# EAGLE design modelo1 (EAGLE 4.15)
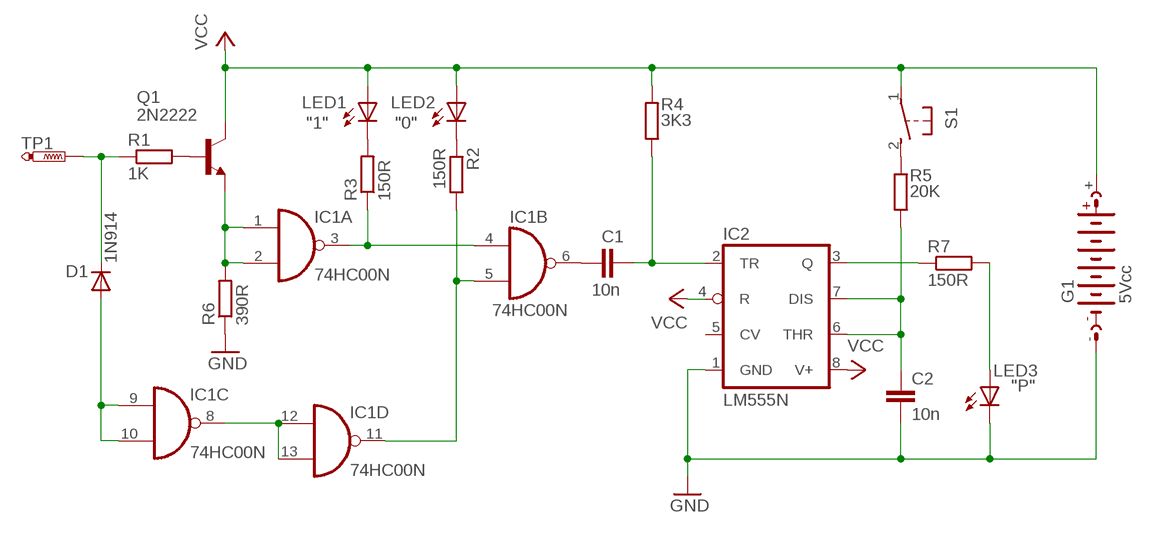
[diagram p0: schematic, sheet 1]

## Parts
C1  10n  C-EU050-030X075  [C050-030X075]
C2  10n  C-EU050-030X075  [C050-030X075]
D1  1N914  DIODE-D-5  [D-5]
G1  5Vcc  AB9V  [AB9V]
IC1  74HC00N  [DIL14]
IC2  LM555N  [DIL08]
LED1  "1"  LED3MM  [LED3MM]
LED2  "0"  LED3MM  [LED3MM]
LED3  "P"  LED3MM  [LED3MM]
Q1  2N2222  [TO18]
R1  1K  R-EU_0204/7  [0204/7]
R2  150R  R-EU_0204/7  [0204/7]
R3  150R  R-EU_0204/7  [0204/7]
R4  3K3  R-EU_0204/7  [0204/7]
R5  20K  R-EU_0204/7  [0204/7]
R6  390R  R-EU_0204/7  [0204/7]
R7  150R  R-EU_0204/7  [0204/7]
S1  31-XX  [B3F-31XX]
TP1  PTR1PAD1-17  [P1-17]

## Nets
GND: C2.2 G1.- IC2.1(GND) LED3.K(C) R6.1
N$1: D1.C R1.1 TP1.1(TP)
N$2: Q1.2(B) R1.2
N$3: LED2.K(C) R2.1
N$4: LED1.K(C) R3.2
N$5: IC1.3(A:O) IC1.4(B:I0) R3.1
N$6: IC1.5(B:I1) IC1.11(D:O) R2.2
N$7: C1.1 IC1.6(B:O)
N$8: IC1.1(A:I0) IC1.2(A:I1) Q1.1(E) R6.2
N$9: D1.A IC1.9(C:I0) IC1.10(C:I1)
N$10: IC1.8(C:O) IC1.12(D:I0) IC1.13(D:I1)
N$11: C1.2 IC2.2(TR) R4.1
N$12: IC2.3(Q) R7.1
N$13: C2.1 IC2.6(THR) IC2.7(DIS) R5.1
N$14: R5.2 S1.2(S)
N$15: LED3.A R7.2
VCC: G1.+ IC2.4(R) IC2.8(V+) LED1.A LED2.A Q1.3(C) R4.2 S1.1(P)
Unconnected: IC2.5(CV)

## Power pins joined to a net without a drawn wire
GND: IC1.7(P:GND)
VCC: IC1.14(P:VCC)

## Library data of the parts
C1 C2 = rcl:C-EU: CAPACITOR, European symbol
D1 = diode:DIODE-: DIODE
G1 = battery:AB9V: 9-V BATTERY CLIP
IC1 = 74xx-eu:74*00: Quad 2-input NAND gate
IC2 = linear:*555: TIMER
LED1-LED3 = led:LED: LED
Q1 = transistor-npn:2N2222*: NPN Transistor
R1-R7 = rcl:R-EU_: RESISTOR, European symbol
S1 = switch-omron:31-XX: OMRON SWITCH
TP1 = testpad:PTR1: TEST PIN

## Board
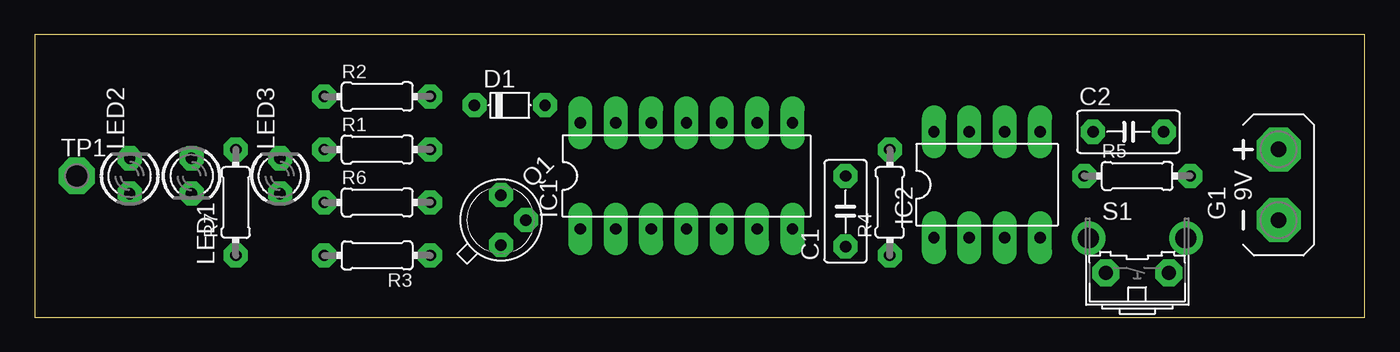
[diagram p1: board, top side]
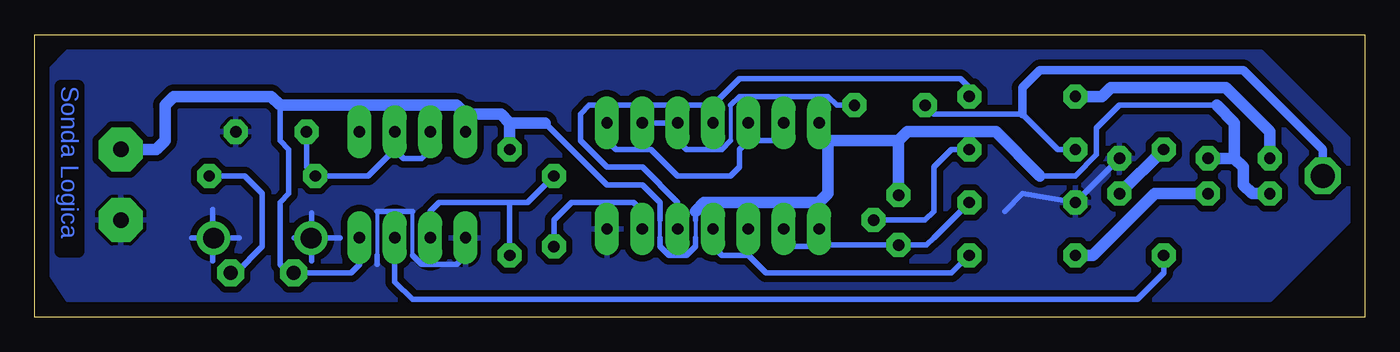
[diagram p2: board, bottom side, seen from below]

Size 95.55 x 20.31 mm. Coordinates in mm from the lower left corner, seen from the top.
Outline: 0,0 95.55,0 95.55,20.31 0,20.31 0,0
Copper layers (1*16): Top 0.035mm / dielectric 1.5mm / Bottom 0.035mm
Design rules "redondo": minimum track width 10mil, minimum drill 3mil, track to track 18mil, track to pad 18mil, pad to pad 18mil, via to via 18mil, smd to smd 8mil, copper to edge 40mil, drill to drill 8mil, minimum pad ring 18mil, minimum via ring 8mil, stop-mask expansion 4mil, vias tented up to drill 0mil, thermal gap 10mil

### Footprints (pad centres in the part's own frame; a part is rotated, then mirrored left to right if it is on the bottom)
C050-030X075 = drill 0.813 octagon: 1 -2.54,0; 2 2.54,0
D-5 = drill 0.813 octagon: A 2.54,0; C -2.54,0
AB9V = drill 1.118 pad 3.15 octagon: + 0,2.54; - 0,-2.54
DIL14 = drill 0.813 long: 1 -7.62,-3.81; 2 -5.08,-3.81; 3 -2.54,-3.81; 4 0,-3.81; 5 2.54,-3.81; 6 5.08,-3.81; 7 7.62,-3.81; 8 7.62,3.81; 9 5.08,3.81; 10 2.54,3.81; 11 0,3.81; 12 -2.54,3.81; 13 -5.08,3.81; 14 -7.62,3.81
DIL08 = drill 0.813 long: 1 -3.81,-3.81; 2 -1.27,-3.81; 3 1.27,-3.81; 4 3.81,-3.81; 5 3.81,3.81; 6 1.27,3.81; 7 -1.27,3.81; 8 -3.81,3.81
LED3MM = drill 0.813 octagon: A -1.27,0; K 1.27,0
TO18 = drill 0.813 octagon: 1 -1.27,-1.27; 2 1.27,-1.27; 3 1.27,1.27
0204/7 = drill 0.813 octagon: 1 -3.81,0; 2 3.81,0
B3F-31XX = drill 1.016 octagon: 1 -2.261,-1.245; 2 2.261,-1.245 | drill 1.499 pad 2.159 round: 3 -3.505,1.245; 4 3.505,1.245
P1-17 = drill 1.702 pad 2.54 octagon: 1 0,0

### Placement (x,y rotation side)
C1  58.25,7.62 90 top
C2  78.58,13.33 0 top
D1  34.12,15.24 0 top
G1  89.37,9.52 0 top
IC1  46.82,10.15 0 top
IC2  68.41,9.52 0 top
LED1  11.27,10.15 270 top
LED2  6.82,10.15 90 top
LED3  17.61,10.15 90 top
Q1  33.49,6.98 45 top
R1  24.6,12.06 0 top
R2  24.6,15.87 0 top
R3  24.6,4.44 180 top
R4  61.43,8.25 90 top
R5  79.21,10.15 0 top
R6  24.6,8.25 0 top
R7  14.44,8.25 90 top
S1  79.21,4.44 0 top
TP1  3.01,10.15 0 top

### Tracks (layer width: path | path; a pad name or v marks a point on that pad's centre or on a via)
GND
  Bottom 0.305: 68.41,4.44 68.41,7.62 | 70.95,7.62 70.95,4.44
  Bottom 0.406: IC2.1 64.61,4.44 65.24,3.8 67.78,3.8 68.41,4.44 | 68.41,7.62 70.95,7.62 | 70.95,4.44 70.95,3.8 | 25.87,7.62 24.6,8.88 R6.1 LED3.K | 75.65,4.06 75.65,7.49 | 80.86,5.71 84.29,5.71 | 82.77,4.06 82.77,7.74 | 73.62,5.71 76.92,5.71
  pour Bottom: 1.1,6.98 1.1,12.7 7.46,19.05 93.18,19.05 94.45,17.77 94.45,3.17 93.18,1.27 6.82,1.27
N$1
  Bottom 0.406: R1.1 22.06,12.06 24.6,14.6 30.95,14.6 D1.C
  Bottom 0.61: TP1.1 3.01,12.06 8.73,17.77 23.33,17.77 24.6,16.51 24.6,14.6
N$2
  Bottom 0.406: R1.2 29.68,12.06 30.95,10.79 30.95,7.62 31.58,6.98 Q1.2 35.39,6.98
N$3
  Bottom 0.813: LED2.K 6.82,13.33 10,16.51 18.25,16.51 18.88,15.87 R2.1
N$4
  Bottom 0.813: LED1.K 15.08,8.88 19.52,4.44 R3.2
N$5
  Bottom 0.406: R3.1 29.68,3.17 30.31,3.17 43.02,3.17 44.28,4.44 | 44.28,4.44 IC1.3 | IC1.4 46.82,5.08 46.19,4.44 44.28,4.44
N$6
  Bottom 0.406: R2.2 28.41,16.51 29.04,17.14 44.92,17.14 46.82,15.24 | 46.82,15.24 IC1.11 | IC1.5 49.37,8.25 51.91,10.79 54.45,10.79 56.35,12.7 56.35,14.6 55.71,15.24 46.82,15.24
N$7
  Bottom 0.406: C1.1 58.25,6.98 56.98,8.25 52.54,8.25 51.91,7.62 IC1.6
N$8
  Bottom 0.406: R6.2 30.95,5.71 31.48,5.18 Q1.1 38.68,5.18 39.2,5.71 | 39.2,5.71 IC1.1 | IC1.2 41.74,5.71 41.11,5.08 39.84,5.08 39.2,5.71
N$9
  Bottom 0.305: 45.55,15.24 45.55,12.7
  Bottom 0.406: IC1.9 IC1.10 49.37,12.7 48.73,12.06 46.19,12.06 45.55,12.7 | 45.55,15.24 44.92,15.87 38.57,15.87 37.94,15.24 D1.A
N$10
  Bottom 0.406: IC1.8 54.45,12.7 53.81,12.06 51.27,12.06 49.37,10.15 45.55,10.15 44.92,10.79 44.92,12.06 44.28,12.7 | 44.28,12.7 IC1.12 | IC1.13 41.74,13.33 42.38,12.7 44.28,12.7
N$11
  Bottom 0.406: C1.2 60.16,8.25 61.43,8.25 | R4.1 61.43,8.25 | IC2.2 67.14,7.62 66.51,8.25 61.43,8.25
N$12
  Bottom 0.406: R7.1 14.44,3.17 16.34,1.27 68.41,1.27 69.69,2.54 IC2.3
N$13
  Bottom 0.406: 69.69,12.06 IC2.6 | 69.69,12.06 69.05,11.43 67.78,11.43 67.14,12.06 IC2.7 | 69.69,12.06 71.59,10.15 R5.1 76.03,10.79 C2.1
N$14
  Bottom 0.406: S1.2 81.09,3.2 79.21,5.08 79.21,8.88 80.48,10.15 R5.2
N$15
  Bottom 0.813: LED3.A R7.2
VCC
  Bottom 0.305: 50.63,5.71 50.63,6.98 | 48.09,6.98 48.09,5.71
  Bottom 0.406: 10.63,15.24 17.61,15.24 19.27,13.58 19.27,11.68 20.79,10.15 23.33,10.15 | 77.94,15.24 77.94,12.7 77.3,12.06 77.3,8.88 77.94,8.25 77.94,3.8 77.33,3.2 S1.1 72.83,3.2 72.22,3.8 IC2.4 | 58.89,13.97 54.45,9.52 51.91,9.52 50.63,8.25 50.63,6.98 | 50.63,5.71 50.63,5.08 50,4.44 48.73,4.44 48.09,5.08 48.09,5.71 | 48.09,7.62 48.09,6.98
  Bottom 0.813: LED2.A 8.09,8.88 8.73,9.52 8.73,10.79 9.36,11.43 | G1.+ 86.83,12.06 86.19,12.7 86.19,15.24 85.56,15.87 78.58,15.87 77.94,15.24 65.24,15.24 64.61,14.6 | 10.63,15.24 9.36,13.97 9.36,11.43 | 9.36,11.43 LED1.A | 61.43,13.97 R4.2 | 61.43,13.97 62.06,14.6 64.61,14.6 | 64.61,14.6 IC2.8 | 58.89,13.97 61.43,13.97 | 48.09,7.62 47.46,8.25 39.2,8.25 38.57,8.88 38.57,12.7 | 23.33,10.15 26.5,13.33 32.85,13.33 33.49,12.7 | 33.49,12.7 Q1.3 | IC1.14 39.2,13.33 38.57,12.7 | 33.49,12.7 38.57,12.7

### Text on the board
Bottom: Sonda Logica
